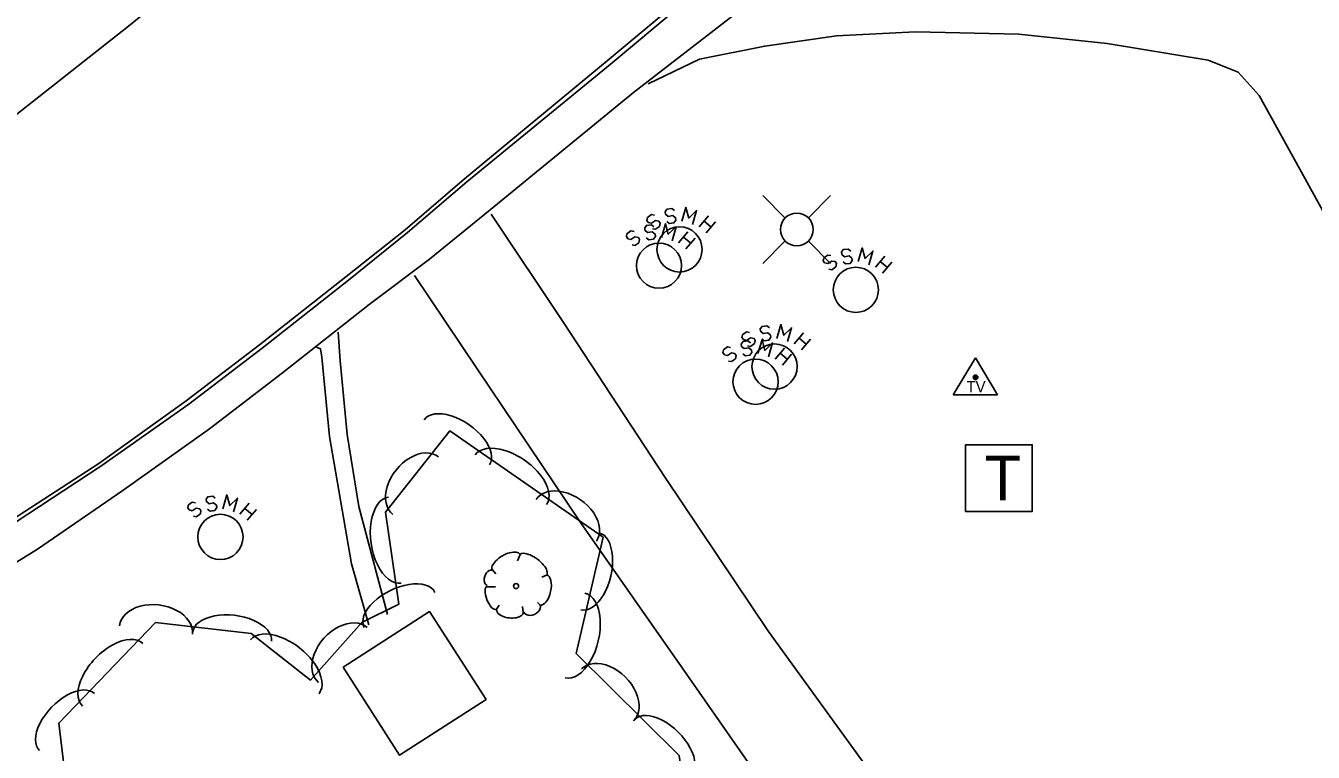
# Model space of a CAD drawing. Extents: x 1042086 to 1119166, y 1916606 to 1927565.
# Drawn here: x 1042945.3 to 1043119, y 1926287.1 to 1926385.1 of the extents above; entities that cross this region are included whole.
import ezdxf

# ---------------------------------------------------------------- set-up
doc = ezdxf.new("R2010")
doc.units = 0
for name, color, linetype in [('S_BUILDING', 7, 'Continuous'), ('S_CURB', 7, 'Continuous'), ('S_EDGE_PAVEMENT', 7, 'Continuous'), ('S_SANITARY_SEWER', 7, 'Continuous'), ('S_SECONDARY_CTL', 7, 'Continuous'), ('S_SIDEWALK', 7, 'Continuous'), ('S_TELEPHONE_UTILITIES', 7, 'Continuous'), ('S_TREE', 7, 'Continuous'), ('S_UTILITY_POLE', 7, 'Continuous')]:
    doc.layers.add(name, color=color, linetype=linetype)

msp = doc.modelspace()

# ---------------------------------------------------------------- linework, layer by layer
at = {"layer": 'S_BUILDING'}
msp.add_lwpolyline([(1042988.12, 1926298.59), (1042999.8, 1926306.11), (1043007.43, 1926294.26), (1042995.75, 1926286.74)], close=True, dxfattribs=at)
at = {"layer": 'S_CURB'}
msp.add_lwpolyline([(1042831.22, 1926263.78), (1042854.05, 1926273.96), (1042878.75, 1926284.86), (1042901.58, 1926295.06), (1042919.82, 1926304.14), (1042932.23, 1926311.01), (1042943.88, 1926318.12), (1042955.46, 1926325.71), (1042967.31, 1926334.09), (1042977.22, 1926341.62), (1042988.88, 1926350.8), (1042996.82, 1926357.2), (1043004.81, 1926364.06), (1043024.16, 1926379.89), (1043043.32, 1926395.94), (1043052.99, 1926404.06), (1043057.29, 1926407.71), (1043060.31, 1926410.24), (1043064.19, 1926413.7), (1043068.9, 1926417.57), (1043087.8, 1926433.94), (1043106.88, 1926450.09), (1043112.19, 1926454.4), (1043126.79, 1926466.85)], dxfattribs=at)
at = {"layer": 'S_EDGE_PAVEMENT'}
for points in [[(1042885.56, 1926337.32), (1042899.04, 1926343.23), (1042920.21, 1926356.51), (1042940.86, 1926370.65), (1042959.18, 1926385.04), (1042978.59, 1926400.81), (1042997.79, 1926416.81), (1043019.29, 1926434.74), (1043038.53, 1926450.69), (1043056.99, 1926467.43), (1043076.46, 1926483.12), (1043095.44, 1926499.39), (1043115.21, 1926516.28), (1043134.32, 1926532.4), (1043153.39, 1926548.56)], [(1042831.04, 1926264.16), (1042853.86, 1926274.37), (1042878.57, 1926285.26), (1042901.34, 1926295.59), (1042919.62, 1926304.57), (1042932.04, 1926311.43), (1042943.54, 1926318.53), (1042955.16, 1926326.06), (1042966.95, 1926334.52), (1042976.85, 1926342.06), (1042988.52, 1926351.24), (1042996.49, 1926357.59), (1043004.5, 1926364.44), (1043023.76, 1926380.37), (1043042.95, 1926396.4), (1043052.64, 1926404.48), (1043056.97, 1926408.1), (1043059.99, 1926410.63), (1043063.91, 1926414.03), (1043068.6, 1926417.93), (1043087.46, 1926434.35), (1043106.52, 1926450.53), (1043111.86, 1926454.8), (1043126.38, 1926467.34)], [(1043088.86, 1926242.2), (1043074.7, 1926262.8), (1043060.2, 1926283.17), (1043045.54, 1926303.43), (1043031.58, 1926324.17), (1043017.88, 1926345.09), (1043008.1, 1926359.68)], [(1043076.61, 1926235.55), (1043062.69, 1926256.32), (1043048.82, 1926277.12), (1043034.49, 1926297.6), (1043020.18, 1926318.1), (1043006.24, 1926338.86), (1042997.75, 1926351.41)]]:
    msp.add_lwpolyline(points, dxfattribs=at)
at = {"layer": 'S_SANITARY_SEWER'}
for p, q in [((1043029.19, 1926359.24), (1043029.11, 1926358.85)), ((1043029.11, 1926358.85), (1043029.31, 1926358.58)), ((1043029.73, 1926359.63), (1043029.19, 1926359.24)), ((1043029.31, 1926358.58), (1043029.73, 1926358.47)), ((1043030.16, 1926359.55), (1043029.73, 1926359.63)), ((1043029.73, 1926358.47), (1043030.28, 1926358.82)), ((1043030.28, 1926358.82), (1043030.74, 1926358.74)), ((1043030.74, 1926358.74), (1043030.9, 1926358.47)), ((1043036.17, 1926358), (1043037.41, 1926359.47)), ((1043036.82, 1926358.78), (1043037.79, 1926357.96)), ((1043038.37, 1926358.66), (1043037.13, 1926357.19)), ((1043026.42, 1926357.05), (1043026.35, 1926356.67)), ((1043026.97, 1926357.44), (1043026.42, 1926357.05)), ((1043027.39, 1926357.36), (1043026.97, 1926357.44)), ((1043030.28, 1926357.65), (1043029.89, 1926357.73)), ((1043030.82, 1926358.04), (1043030.28, 1926357.65)), ((1043030.9, 1926358.47), (1043030.82, 1926358.04)), ((1043033.4, 1926355.81), (1043034.64, 1926357.29)), ((1043026.35, 1926356.67), (1043026.54, 1926356.39)), ((1043026.54, 1926356.39), (1043026.97, 1926356.28)), ((1043026.97, 1926356.28), (1043027.51, 1926356.63)), ((1043027.51, 1926355.46), (1043027.12, 1926355.54)), ((1043027.51, 1926356.63), (1043027.97, 1926356.55)), ((1043028.05, 1926355.85), (1043027.51, 1926355.46)), ((1043027.97, 1926356.55), (1043028.13, 1926356.28)), ((1043028.13, 1926356.28), (1043028.05, 1926355.85)), ((1043034.06, 1926356.59), (1043035.03, 1926355.77)), ((1043035.61, 1926356.47), (1043034.37, 1926355)), ((1043052.98, 1926353.79), (1043052.9, 1926353.41)), ((1043052.9, 1926353.41), (1043053.1, 1926353.13)), ((1043053.52, 1926354.18), (1043052.98, 1926353.79)), ((1043053.95, 1926354.1), (1043053.52, 1926354.18)), ((1043053.52, 1926353.02), (1043054.07, 1926353.37)), ((1043054.07, 1926353.37), (1043054.53, 1926353.29)), ((1043054.53, 1926353.29), (1043054.69, 1926353.02)), ((1043059.96, 1926352.55), (1043061.2, 1926354.03)), ((1043060.61, 1926353.33), (1043061.58, 1926352.51)), ((1043053.1, 1926353.13), (1043053.52, 1926353.02)), ((1043054.07, 1926352.2), (1043053.68, 1926352.28)), ((1043054.61, 1926352.59), (1043054.07, 1926352.2)), ((1043054.69, 1926353.02), (1043054.61, 1926352.59)), ((1043062.16, 1926353.21), (1043060.92, 1926351.74)), ((1043042.02, 1926343.44), (1043041.94, 1926343.05)), ((1043041.94, 1926343.05), (1043042.13, 1926342.78)), ((1043042.56, 1926343.83), (1043042.02, 1926343.44)), ((1043042.98, 1926343.75), (1043042.56, 1926343.83)), ((1043042.56, 1926342.66), (1043043.1, 1926343.01)), ((1043043.1, 1926343.01), (1043043.57, 1926342.94)), ((1043043.57, 1926342.94), (1043043.72, 1926342.66)), ((1043048.99, 1926342.2), (1043050.23, 1926343.67)), ((1043049.65, 1926342.97), (1043050.62, 1926342.16)), ((1043051.2, 1926342.86), (1043049.96, 1926341.39)), ((1043039.45, 1926341.4), (1043039.38, 1926341.02)), ((1043040, 1926341.79), (1043039.45, 1926341.4)), ((1043040.42, 1926341.71), (1043040, 1926341.79)), ((1043042.13, 1926342.78), (1043042.56, 1926342.66)), ((1043043.1, 1926341.85), (1043042.71, 1926341.93)), ((1043043.64, 1926342.24), (1043043.1, 1926341.85)), ((1043043.72, 1926342.66), (1043043.64, 1926342.24)), ((1043046.43, 1926340.16), (1043047.67, 1926341.64)), ((1043039.38, 1926341.02), (1043039.57, 1926340.74)), ((1043039.57, 1926340.74), (1043040, 1926340.63)), ((1043040, 1926340.63), (1043040.54, 1926340.98)), ((1043040.54, 1926339.81), (1043040.15, 1926339.89)), ((1043040.54, 1926340.98), (1043041, 1926340.9)), ((1043041.08, 1926340.2), (1043040.54, 1926339.81)), ((1043041, 1926340.9), (1043041.16, 1926340.63)), ((1043041.16, 1926340.63), (1043041.08, 1926340.2)), ((1043047.09, 1926340.94), (1043048.06, 1926340.12)), ((1043048.64, 1926340.82), (1043047.4, 1926339.35)), ((1042967.25, 1926320.47), (1042967.17, 1926320.09)), ((1042967.79, 1926320.86), (1042967.25, 1926320.47)), ((1042968.22, 1926320.78), (1042967.79, 1926320.86)), ((1042974.22, 1926319.23), (1042975.46, 1926320.71)), ((1042967.17, 1926320.09), (1042967.36, 1926319.82)), ((1042967.36, 1926319.82), (1042967.79, 1926319.7)), ((1042967.79, 1926319.7), (1042968.33, 1926320.05)), ((1042968.33, 1926318.89), (1042967.95, 1926318.96)), ((1042968.33, 1926320.05), (1042968.8, 1926319.97)), ((1042968.88, 1926319.27), (1042968.33, 1926318.89)), ((1042968.8, 1926319.97), (1042968.95, 1926319.7)), ((1042968.95, 1926319.7), (1042968.88, 1926319.27)), ((1042974.88, 1926320.01), (1042975.85, 1926319.2)), ((1042976.43, 1926319.89), (1042975.19, 1926318.42))]:
    msp.add_line(p, q, dxfattribs=at)
for points in [[(1043032.83, 1926360.17), (1043032.48, 1926360.44), (1043031.83, 1926360.37), (1043031.59, 1926360.02), (1043031.63, 1926359.71), (1043031.98, 1926359.4), (1043032.6, 1926359.51), (1043032.99, 1926359.2), (1043033.03, 1926358.89), (1043032.76, 1926358.51), (1043032.14, 1926358.43), (1043031.79, 1926358.7)], [(1043035.27, 1926358.31), (1043035.82, 1926360.17), (1043034.77, 1926359.16), (1043034.38, 1926360.6), (1043033.84, 1926358.74)], [(1043030.07, 1926357.98), (1043029.72, 1926358.25), (1043029.06, 1926358.18), (1043028.83, 1926357.83), (1043028.86, 1926357.52), (1043029.21, 1926357.21), (1043029.83, 1926357.32), (1043030.22, 1926357.01), (1043030.26, 1926356.7), (1043029.99, 1926356.32), (1043029.37, 1926356.24), (1043029.02, 1926356.51)], [(1043032.51, 1926356.12), (1043033.05, 1926357.98), (1043032, 1926356.98), (1043031.62, 1926358.41), (1043031.07, 1926356.55)], [(1043059.06, 1926352.86), (1043059.61, 1926354.72), (1043058.56, 1926353.72), (1043058.17, 1926355.15), (1043057.63, 1926353.29)], [(1043056.62, 1926354.72), (1043056.27, 1926354.99), (1043055.62, 1926354.92), (1043055.38, 1926354.57), (1043055.42, 1926354.26), (1043055.77, 1926353.95), (1043056.39, 1926354.06), (1043056.78, 1926353.75), (1043056.82, 1926353.44), (1043056.55, 1926353.06), (1043055.93, 1926352.98), (1043055.58, 1926353.25)], [(1043045.66, 1926344.37), (1043045.31, 1926344.64), (1043044.65, 1926344.56), (1043044.42, 1926344.21), (1043044.46, 1926343.9), (1043044.81, 1926343.59), (1043045.43, 1926343.71), (1043045.81, 1926343.4), (1043045.85, 1926343.09), (1043045.58, 1926342.7), (1043044.96, 1926342.63), (1043044.61, 1926342.9)], [(1043048.1, 1926342.51), (1043048.64, 1926344.37), (1043047.6, 1926343.36), (1043047.21, 1926344.8), (1043046.67, 1926342.94)], [(1043043.1, 1926342.33), (1043042.75, 1926342.6), (1043042.09, 1926342.53), (1043041.86, 1926342.18), (1043041.9, 1926341.87), (1043042.24, 1926341.56), (1043042.86, 1926341.67), (1043043.25, 1926341.36), (1043043.29, 1926341.05), (1043043.02, 1926340.67), (1043042.4, 1926340.59), (1043042.05, 1926340.86)], [(1043045.54, 1926340.47), (1043046.08, 1926342.33), (1043045.03, 1926341.33), (1043044.65, 1926342.76), (1043044.1, 1926340.9)], [(1042970.89, 1926321.4), (1042970.54, 1926321.68), (1042969.88, 1926321.6), (1042969.65, 1926321.25), (1042969.69, 1926320.94), (1042970.04, 1926320.63), (1042970.66, 1926320.75), (1042971.05, 1926320.44), (1042971.08, 1926320.13), (1042970.81, 1926319.74), (1042970.19, 1926319.66), (1042969.84, 1926319.93)], [(1042973.33, 1926319.54), (1042973.87, 1926321.4), (1042972.83, 1926320.4), (1042972.44, 1926321.83), (1042971.9, 1926319.97)]]:
    msp.add_lwpolyline(points, dxfattribs=at)
for centre in [(1043033.52, 1926354.94), (1043030.75, 1926352.75), (1043057.31, 1926349.49), (1043046.34, 1926339.14), (1043043.78, 1926337.1), (1042971.58, 1926316.17)]:
    msp.add_circle(centre, 3.05, dxfattribs=at)
at = {"layer": 'S_SECONDARY_CTL'}
for p, q in [((1043073.46, 1926340.3), (1043070.45, 1926335.35)), ((1043073.46, 1926340.3), (1043076.41, 1926335.35)), ((1043070.45, 1926335.35), (1043076.41, 1926335.35))]:
    msp.add_line(p, q, dxfattribs=at)
for radius in [0.311, 0.183, 0.103]:
    msp.add_circle((1043073.46, 1926337.69), radius, dxfattribs=at)
at = {"layer": 'S_SIDEWALK'}
for points in [[(1042807.55, 1926248.25), (1042833.07, 1926259.74), (1042855.92, 1926269.9), (1042880.65, 1926280.74), (1042903.37, 1926291.15), (1042921.76, 1926299.92), (1042934.22, 1926306.68), (1042946.9, 1926314.51), (1042958.28, 1926322.32), (1042970.1, 1926330.73), (1042979.97, 1926338.32), (1042991.63, 1926347.5), (1042999.8, 1926353.63), (1043007.98, 1926360.26), (1043027.31, 1926376.11), (1043047.09, 1926391.43)], [(1043065.34, 1926384.3), (1043054.68, 1926383.75), (1043045.02, 1926382.37), (1043036.21, 1926380.59), (1043029.29, 1926377.27)], [(1043065.34, 1926384.3), (1043079.28, 1926383.96), (1043091.23, 1926382.71), (1043104.84, 1926380.47), (1043108.9, 1926378.83), (1043111.71, 1926375.68), (1043121.04, 1926358.83), (1043138.45, 1926328.23), (1043142.51, 1926321.25), (1043143.01, 1926317.49), (1043141.95, 1926313.31)], [(1042994.11, 1926305.71), (1042990.26, 1926320.27), (1042988.69, 1926329.98), (1042987.74, 1926339.91), (1042987.46, 1926343.79)], [(1042991.6, 1926304.3), (1042989.26, 1926312.54), (1042986.31, 1926329.71), (1042985.25, 1926340.4), (1042985.09, 1926341.53), (1042984.56, 1926341.77)]]:
    msp.add_lwpolyline(points, dxfattribs=at)
at = {"layer": 'S_TELEPHONE_UTILITIES'}
msp.add_lwpolyline([(1043072.12, 1926319.61), (1043072.12, 1926328.61), (1043081.12, 1926328.61), (1043081.12, 1926319.61)], close=True, dxfattribs=at)
at = {"layer": 'S_TREE'}
for p, q in [((1043012.03, 1926313.79), (1043011.64, 1926312.94)), ((1043008.23, 1926311.78), (1043008.73, 1926311.2)), ((1043015.59, 1926311), (1043014.93, 1926310.73)), ((1043007.57, 1926309.45), (1043008.69, 1926309.45)), ((1043008.73, 1926306.28), (1043009.2, 1926306.97)), ((1043012.41, 1926306.01), (1043012.34, 1926306.78)), ((1043014.82, 1926306.9), (1043014.35, 1926307.32))]:
    msp.add_line(p, q, dxfattribs=at)
msp.add_lwpolyline([(1042957.78, 1926269.39), (1042951.48, 1926276.86), (1042949.76, 1926291.08), (1042962.83, 1926304.63), (1042975.71, 1926303.17), (1042983.74, 1926296.86), (1042990.65, 1926304.63), (1042995.63, 1926307.09), (1042993.83, 1926319.51), (1043002.53, 1926330.47), (1043023.24, 1926316.12), (1043019.59, 1926300.44), (1043033.47, 1926286.69), (1043035.66, 1926271.48), (1043025.43, 1926255.27), (1043001.07, 1926256.47), (1042979.96, 1926269.75)], close=True, dxfattribs=at)
msp.add_circle((1043011.47, 1926309.55), 0.341, dxfattribs=at)
for centre, major_axis, ratio, start_param, end_param in [((1043003.48, 1926328.93), (4.39, -3.04), 0.540699, 0, 3.141593), ((1042997.93, 1926323.08), (3.08, 3.88), 0.685311, 0, 3.141593), ((1043010.76, 1926323.88), (4.82, -3.34), 0.55008, 0, 3.141593), ((1043018.23, 1926318.4), (4.07, -2.82), 0.685311, 0, 3.141593), ((1042995.11, 1926315.74), (-0.84, 5.81), 0.55008, 0, 3.141593), ((1043021.43, 1926311.53), (-1.21, -5.21), 0.540699, 0, 3.141593), ((1043010.13, 1926312.75), (1.86, 1.08), 0.471018, 0, 3.141593), ((1043013.79, 1926312.43), (-1.81, 1.36), 0.405113, 3.141593, 6.283186), ((1043007.9, 1926310.64), (0.31, 1.03), 0.646762, 0, 3.141593), ((1042995.74, 1926306.33), (4.79, 2.37), 0.540699, 0, 3.141593), ((1043015.14, 1926309.02), (0.46, 2.04), 0.482994, 3.141593, 6.283185), ((1043008.2, 1926307.99), (-0.61, 1.6), 0.420543, 6.283185, 9.424777), ((1043019.42, 1926302.89), (-1.33, -5.72), 0.55008, 0, 3.141593), ((1042962.88, 1926303.63), (4.92, -0.56), 0.685311, 0, 3.141593), ((1043010.66, 1926306.21), (-1.83, 0.19), 0.529943, 0, 3.141593), ((1043013.62, 1926306.5), (1.09, 0.46), 0.711534, 3.141592, 6.283185), ((1042973.15, 1926302.73), (5.31, -0.6), 0.540699, 0, 3.141593), ((1042988.08, 1926300.25), (3.29, 3.7), 0.685311, 0, 3.141593), ((1042957.04, 1926297.58), (4.07, 4.22), 0.55008, 0, 3.141593), ((1042980.27, 1926298.66), (4.61, -3.63), 0.55008, 0, 3.141593), ((1043023.81, 1926294.88), (3.52, -3.49), 0.685311, 0, 3.141593), ((1042950.88, 1926291.2), (3.71, 3.85), 0.540699, 0, 3.141593), ((1043031.31, 1926287.81), (3.8, -3.76), 0.540699, 0, 3.141593)]:
    msp.add_ellipse(centre, major_axis=major_axis, ratio=ratio, start_param=start_param, end_param=end_param, dxfattribs=at)
at = {"layer": 'S_UTILITY_POLE'}
for p, q in [((1043047.75, 1926359.21), (1043044.76, 1926362.2)), ((1043050.92, 1926359.21), (1043053.91, 1926362.2)), ((1043047.75, 1926356.04), (1043044.76, 1926353.05)), ((1043050.92, 1926356.04), (1043053.91, 1926353.05))]:
    msp.add_line(p, q, dxfattribs=at)
msp.add_circle((1043049.34, 1926357.63), 2.21, dxfattribs=at)

# ---------------------------------------------------------------- texts
at = {"layer": 'S_SECONDARY_CTL'}
msp.add_text('TV', height=1.5, rotation=360, dxfattribs=at).set_placement((1043072.25, 1926335.68))
at = {"layer": 'S_TELEPHONE_UTILITIES'}
msp.add_text('T', height=6, rotation=360, dxfattribs=at).set_placement((1043074.69, 1926321.11))

doc.saveas('drawing.dxf')
